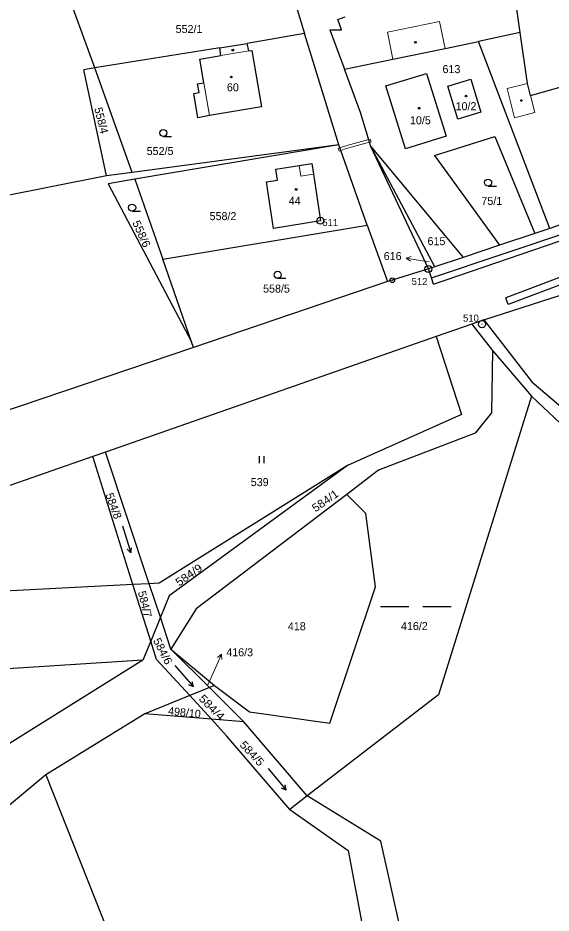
# Model space of a CAD drawing. Extents: x -664548 to -662415, y -1069720 to -1068208.
# Drawn here: x -663871.7 to -663758.5, y -1069095.9 to -1068905.8 of the extents above; entities that cross this region are included whole.
import ezdxf
from ezdxf.enums import TextEntityAlignment as Align

# ---------------------------------------------------------------- set-up
doc = ezdxf.new("R2010")
doc.units = 0
doc.header["$LTSCALE"] = 0.68
for name, color, linetype, lineweight in [('1', 7, 'Continuous', 25), ('13', 7, 'Continuous', 13), ('3', 7, 'Continuous', 25), ('4', 7, 'Continuous', 13), ('5', 7, 'Continuous', 25), ('7', 7, 'Continuous', 13), ('8', 7, 'Continuous', 25)]:
    doc.layers.add(name, color=color, linetype=linetype, lineweight=lineweight)
doc.layers.add('2', color=7, linetype='Continuous')

msp = doc.modelspace()

# ---------------------------------------------------------------- linework, layer by layer
at = {"layer": '1'}
for p, q in [((-663765.02, -1068908.87), (-663769.59, -1068876.23)), ((-663815.78, -1068892.97), (-663810.81, -1068909.09)), ((-663855.38, -1068916.4), (-663860.72, -1068901.56)), ((-663803.77, -1068906.09), (-663802.22, -1068905.52)), ((-663802.95, -1068908.29), (-663803.77, -1068906.09)), ((-663810.81, -1068909.09), (-663823.01, -1068911.18)), ((-663803.51, -1068932.74), (-663810.81, -1068909.09)), ((-663805.42, -1068908.29), (-663802.95, -1068908.29)), ((-663805.42, -1068908.29), (-663802.33, -1068916.65)), ((-663765.02, -1068908.87), (-663773.9, -1068910.78)), ((-663763.5, -1068919.69), (-663765.02, -1068908.87)), ((-663828.84, -1068912.12), (-663823.01, -1068911.18)), ((-663822.67, -1068912.77), (-663823.01, -1068911.18)), ((-663780.97, -1068912.24), (-663773.9, -1068910.78)), ((-663758.76, -1068950.5), (-663773.9, -1068910.78)), ((-663828.84, -1068912.12), (-663855.38, -1068916.4)), ((-663828.59, -1068913.77), (-663828.84, -1068912.12)), ((-663822.67, -1068912.77), (-663822.03, -1068912.67)), ((-663822.03, -1068912.67), (-663819.96, -1068924.67)), ((-663792.04, -1068914.52), (-663780.97, -1068912.24)), ((-663833.07, -1068914.53), (-663828.59, -1068913.77)), ((-663832.2, -1068919.56), (-663833.07, -1068914.53)), ((-663802.33, -1068916.65), (-663792.04, -1068914.52)), ((-663855.38, -1068916.4), (-663857.7, -1068916.78)), ((-663852.85, -1068939.32), (-663857.7, -1068916.78)), ((-663847.39, -1068938.59), (-663855.38, -1068916.4)), ((-663798.92, -1068925.89), (-663802.33, -1068916.65)), ((-663793.52, -1068920.22), (-663784.92, -1068917.55)), ((-663784.92, -1068917.55), (-663780.77, -1068930.91)), ((-663780.4, -1068920.27), (-663775.53, -1068918.77)), ((-663775.53, -1068918.77), (-663773.37, -1068925.8)), ((-663833.52, -1068919.79), (-663832.2, -1068919.56)), ((-663833.19, -1068921.64), (-663833.52, -1068919.79)), ((-663789.37, -1068933.59), (-663793.52, -1068920.22)), ((-663778.23, -1068927.31), (-663780.4, -1068920.27)), ((-663762.84, -1068922.22), (-663763.5, -1068919.69)), ((-663762.84, -1068922.22), (-663752.94, -1068919.42)), ((-663834.33, -1068921.82), (-663833.19, -1068921.64)), ((-663833.5, -1068926.99), (-663834.33, -1068921.82)), ((-663819.96, -1068924.67), (-663831, -1068926.53)), ((-663796.72, -1068933.1), (-663798.92, -1068925.89)), ((-663773.37, -1068925.8), (-663778.23, -1068927.31)), ((-663831, -1068926.53), (-663833.5, -1068926.99)), ((-663780.77, -1068930.91), (-663789.37, -1068933.59)), ((-663783.24, -1068935.02), (-663770.43, -1068930.97)), ((-663770.43, -1068930.97), (-663761.92, -1068951.55)), ((-663803.51, -1068932.74), (-663847.39, -1068938.59)), ((-663803.51, -1068932.74), (-663846.87, -1068940.04)), ((-663797.51, -1068949.76), (-663803.51, -1068932.74)), ((-663796.72, -1068933.1), (-663777.14, -1068956.63)), ((-663783.18, -1068958.64), (-663796.72, -1068933.1)), ((-663784.52, -1068959.09), (-663796.72, -1068933.1)), ((-663783.24, -1068935.02), (-663769.42, -1068954.05)), ((-663816.92, -1068937.88), (-663811.98, -1068937.12)), ((-663811.98, -1068937.12), (-663809.28, -1068936.71)), ((-663809.28, -1068936.71), (-663808.94, -1068938.96)), ((-663852.85, -1068939.32), (-663904.59, -1068949.64)), ((-663847.39, -1068938.59), (-663852.85, -1068939.32)), ((-663816.56, -1068940.2), (-663816.92, -1068937.88)), ((-663808.94, -1068938.96), (-663807.43, -1068948.85)), ((-663846.87, -1068940.04), (-663852.49, -1068940.99)), ((-663852.49, -1068940.99), (-663834.81, -1068974.56)), ((-663846.87, -1068940.04), (-663840.93, -1068957.04)), ((-663818.93, -1068940.59), (-663816.56, -1068940.2)), ((-663817.39, -1068950.47), (-663818.93, -1068940.59)), ((-663783.89, -1068961.01), (-663731.04, -1068943.25)), ((-663783.45, -1068962.35), (-663730.69, -1068944.3)), ((-663807.43, -1068948.85), (-663817.39, -1068950.47)), ((-663720.97, -1068947.42), (-663768.1, -1068965.24)), ((-663720.5, -1068948.84), (-663767.57, -1068966.64)), ((-663752.88, -1068948.45), (-663758.76, -1068950.5)), ((-663840.93, -1068957.04), (-663797.51, -1068949.76)), ((-663797.51, -1068949.76), (-663793.21, -1068961.78)), ((-663758.76, -1068950.5), (-663761.92, -1068951.55)), ((-663761.92, -1068951.55), (-663769.42, -1068954.05)), ((-663769.42, -1068954.05), (-663777.14, -1068956.63)), ((-663772.74, -1068969.94), (-663725.06, -1068954.55)), ((-663777.14, -1068956.63), (-663783.18, -1068958.64)), ((-663834.81, -1068974.56), (-663840.93, -1068957.04)), ((-663783.18, -1068958.64), (-663784.52, -1068959.09)), ((-663784.52, -1068959.09), (-663792.19, -1068961.5)), ((-663783.89, -1068961.01), (-663784.52, -1068959.09)), ((-663793.21, -1068961.78), (-663834.39, -1068975.76)), ((-663792.19, -1068961.5), (-663793.21, -1068961.78)), ((-663783.45, -1068962.35), (-663783.89, -1068961.01)), ((-663767.57, -1068966.64), (-663768.1, -1068965.24)), ((-663772.74, -1068969.94), (-663775.29, -1068970.83)), ((-663772.74, -1068969.94), (-663762.53, -1068983.07)), ((-663775.29, -1068970.83), (-663782.85, -1068973.47)), ((-663782.85, -1068973.47), (-663853.05, -1068997.99)), ((-663782.85, -1068973.47), (-663777.52, -1068990)), ((-663834.39, -1068975.76), (-663899.9, -1068997.91)), ((-663834.39, -1068975.76), (-663834.81, -1068974.56)), ((-663770.9, -1068976.39), (-663762.6, -1068986.14)), ((-663762.53, -1068983.07), (-663748.36, -1068995.22)), ((-663762.6, -1068986.14), (-663782.35, -1069049.55)), ((-663762.6, -1068986.14), (-663750.68, -1068997.45)), ((-663777.52, -1068990), (-663801.7, -1069000.84)), ((-663771.11, -1068989.7), (-663774.57, -1068993.97)), ((-663774.57, -1068993.97), (-663795.13, -1069001.88)), ((-663853.05, -1068997.99), (-663855.8, -1068998.95)), ((-663843.78, -1069025.98), (-663853.05, -1068997.99)), ((-663855.8, -1068998.95), (-663894.44, -1069012.45)), ((-663847.26, -1069026.15), (-663855.8, -1068998.95)), ((-663801.7, -1069000.84), (-663841.7, -1069025.88)), ((-663801.7, -1069000.84), (-663839.6, -1069028.51)), ((-663795.13, -1069001.88), (-663801.83, -1069006.98)), ((-663801.83, -1069006.98), (-663833.81, -1069031.33)), ((-663797.83, -1069011.05), (-663801.83, -1069006.98)), ((-663795.78, -1069026.6), (-663797.83, -1069011.05)), ((-663847.26, -1069026.15), (-663875.95, -1069027.59)), ((-663843.78, -1069025.98), (-663847.26, -1069026.15)), ((-663843.49, -1069038.15), (-663847.26, -1069026.15)), ((-663841.7, -1069025.88), (-663843.78, -1069025.98)), ((-663841.44, -1069033.06), (-663843.78, -1069025.98)), ((-663805.46, -1069055.59), (-663795.78, -1069026.6)), ((-663839.6, -1069028.51), (-663841.44, -1069033.06)), ((-663833.81, -1069031.33), (-663839.18, -1069039.89)), ((-663841.44, -1069033.06), (-663843.49, -1069038.15)), ((-663839.18, -1069039.89), (-663841.44, -1069033.06)), ((-663843.49, -1069038.15), (-663845.14, -1069042.24)), ((-663842.26, -1069042.07), (-663843.49, -1069038.15)), ((-663830.98, -1069048.05), (-663839.18, -1069039.89)), ((-663839.18, -1069039.89), (-663829.93, -1069047.62)), ((-663845.14, -1069042.24), (-663902.32, -1069045.83)), ((-663845.14, -1069042.24), (-663874.07, -1069060.3)), ((-663835.19, -1069049.75), (-663842.26, -1069042.07)), ((-663830.98, -1069048.05), (-663835.19, -1069049.75)), ((-663829.93, -1069047.62), (-663830.98, -1069048.05)), ((-663823.71, -1069055.28), (-663830.98, -1069048.05)), ((-663829.93, -1069047.62), (-663822.51, -1069053.21)), ((-663835.19, -1069049.75), (-663844.7, -1069053.6)), ((-663830.61, -1069054.73), (-663835.19, -1069049.75)), ((-663782.35, -1069049.55), (-663810.24, -1069071.06)), ((-663844.7, -1069053.6), (-663865.77, -1069066.56)), ((-663830.61, -1069054.73), (-663844.7, -1069053.6)), ((-663822.51, -1069053.21), (-663805.46, -1069055.59)), ((-663823.71, -1069055.28), (-663830.61, -1069054.73)), ((-663827.29, -1069058.33), (-663830.61, -1069054.73)), ((-663810.24, -1069071.06), (-663823.71, -1069055.28)), ((-663813.97, -1069073.94), (-663827.29, -1069058.33)), ((-663865.77, -1069066.56), (-663883.87, -1069081.66)), ((-663865.77, -1069066.56), (-663839.98, -1069131.55)), ((-663810.24, -1069071.06), (-663813.97, -1069073.94)), ((-663794.6, -1069080.65), (-663810.24, -1069071.06)), ((-663813.97, -1069073.94), (-663801.58, -1069082.65)), ((-663790.14, -1069100.67), (-663794.6, -1069080.65)), ((-663801.58, -1069082.65), (-663798.08, -1069101.18))]:
    msp.add_line(p, q, dxfattribs=at)
msp.add_lwpolyline([(-663775.29, -1068970.83), (-663770.9, -1068976.39), (-663771.11, -1068989.7)], dxfattribs=at)
at = {"layer": '13'}
for points in [[(-663800.89, -1068933.24), (-663797.01, -1068932.16), (-663797.18, -1068931.58), (-663801.05, -1068932.66), (-663802.5, -1068933.06), (-663803.29, -1068933.36), (-663803.09, -1068933.93), (-663802.38, -1068933.66)], [(-663796.85, -1068931.49), (-663797.18, -1068931.58), (-663797.01, -1068932.16), (-663796.69, -1068932.07)], [(-663803.47, -1068934.07), (-663803.09, -1068933.93), (-663803.29, -1068933.36), (-663803.68, -1068933.5)]]:
    msp.add_lwpolyline(points, close=True, dxfattribs=at)
at = {"layer": '3'}
for p, q in [((-663840.803, -1068930.96), (-663839.053, -1068930.96)), ((-663771.833, -1068941.5), (-663770.083, -1068941.5)), ((-663847.423, -1068946.82), (-663845.673, -1068946.82)), ((-663816.533, -1068961.08), (-663814.783, -1068961.08)), ((-663820.401, -1069000.36), (-663820.401, -1068998.86)), ((-663819.4, -1069000.36), (-663819.4, -1068998.86)), ((-663847.726, -1069019.398), (-663848.491, -1069018.61)), ((-663794.669, -1069030.84), (-663788.669, -1069030.84)), ((-663785.669, -1069030.84), (-663779.669, -1069030.84)), ((-663834.407, -1069047.863), (-663835.427, -1069047.454)), ((-663814.687, -1069069.797), (-663815.699, -1069069.371))]:
    msp.add_line(p, q, dxfattribs=at)
for points in [[(-663849.48, -1069013.66), (-663847.726, -1069019.398), (-663847.532, -1069018.317)], [(-663838.343, -1069043.334), (-663834.407, -1069047.863), (-663834.67, -1069046.796)], [(-663818.544, -1069065.201), (-663814.687, -1069069.797), (-663814.931, -1069068.726)]]:
    msp.add_lwpolyline(points, dxfattribs=at)
for centre in [(-663840.8029, -1068930.2098), (-663771.8329, -1068940.7498), (-663847.4229, -1068946.0698), (-663816.5329, -1068960.3298)]:
    msp.add_circle(centre, 0.75, dxfattribs=at)
at = {"layer": '4'}
for p, q in [((-663793.2, -1068908.77), (-663782.13, -1068906.53)), ((-663780.97, -1068912.24), (-663782.13, -1068906.53)), ((-663792.04, -1068914.52), (-663793.2, -1068908.77)), ((-663828.59, -1068913.77), (-663822.67, -1068912.77)), ((-663831, -1068926.53), (-663832.2, -1068919.56)), ((-663763.5, -1068919.69), (-663767.79, -1068920.79)), ((-663767.79, -1068920.79), (-663766.21, -1068926.97)), ((-663761.9, -1068925.87), (-663762.84, -1068922.22)), ((-663761.9, -1068925.87), (-663766.21, -1068926.97)), ((-663811.98, -1068937.12), (-663811.63, -1068939.42)), ((-663811.63, -1068939.42), (-663808.94, -1068938.96))]:
    msp.add_line(p, q, dxfattribs=at)
at = {"layer": '5'}
for centre in [(-663787.2568, -1068910.9492), (-663826.0568, -1068912.5992), (-663826.3468, -1068918.3292), (-663776.5368, -1068922.3792), (-663764.7668, -1068923.3092), (-663786.4668, -1068924.9492), (-663812.5968, -1068942.2092)]:
    msp.add_circle(centre, 0.175, dxfattribs=at)
at = {"layer": '7'}
for p, q in [((-663789.214, -1068956.811), (-663788.303, -1068957.462)), ((-663828.449, -1069040.958), (-663829.314, -1069041.67))]:
    msp.add_line(p, q, dxfattribs=at)
for points in [[(-663784.35, -1068957.6), (-663786.25, -1068957.28), (-663789.214, -1068956.811), (-663788.147, -1068956.473)], [(-663831.36, -1069047.44), (-663829.67, -1069043.7), (-663828.449, -1069040.958), (-663828.399, -1069042.077)]]:
    msp.add_lwpolyline(points, dxfattribs=at)
at = {"layer": '8'}
for centre, radius in [((-663807.45, -1068948.8498), 0.75), ((-663807.45, -1068948.8498), 0.03), ((-663784.53, -1068959.0998), 0.75), ((-663784.53, -1068959.0998), 0.03), ((-663792.19, -1068961.4999), 0.5), ((-663792.19, -1068961.4999), 0.0303), ((-663773.13, -1068970.8298), 0.75), ((-663773.13, -1068970.8298), 0.03)]:
    msp.add_circle(centre, radius, dxfattribs=at)

# ---------------------------------------------------------------- texts
at = {"layer": '2'}
for s, p in [('552/1', (-663838.19, -1068908.975)), ('613', (-663781.52, -1068917.495)), ('60', (-663827.3, -1068921.354)), ('10/2', (-663778.74, -1068925.375)), ('10/5', (-663788.43, -1068928.365)), ('552/5', (-663844.34, -1068934.895)), ('44', (-663814.17, -1068945.455)), ('75/1', (-663773.26, -1068945.495)), ('558/2', (-663830.98, -1068948.725)), ('615', (-663784.7, -1068954.045)), ('558/5', (-663819.62, -1068964.125)), ('539', (-663822.24, -1069005.235)), ('418', (-663814.36, -1069035.854)), ('416/2', (-663790.34, -1069035.814)), ('416/3', (-663827.44, -1069041.385))]:
    msp.add_text(s, height=1.7, dxfattribs=at).set_placement(p)
for s, rotation, p in [('558/4', 284, (-663855.492, -1068924.992)), ('584/8', 290, (-663853.119, -1069007.055)), ('584/7', 284, (-663846.222, -1069027.752)), ('498/10', 354, (-663839.864, -1069053.792))]:
    msp.add_text(s, height=1.7, rotation=rotation, dxfattribs=at).set_placement(p)
for s, rotation, width, p in [('558/6', 294, 1.05, (-663847.418, -1068949.252)), ('584/1', 35, 1.1, (-663808.506, -1069010.838)), ('584/9', 35, 1.1, (-663837.466, -1069026.598)), ('584/6', 297, 1.05, (-663843.028, -1069038.022)), ('584/4', 315, 1.15, (-663833.42, -1069050.54)), ('584/5', 313, 1.1, (-663824.73, -1069060.319))]:
    msp.add_text(s, height=1.7, rotation=rotation, dxfattribs=dict(at, width=width)).set_placement(p)
msp.add_text('616', height=1.7, dxfattribs=at).set_placement((-663790.209, -1068957.215), align=Align.RIGHT)
at = {"layer": '8'}
for s, p in [('511', (-663803.688, -1068949.985)), ('512', (-663784.729, -1068962.507)), ('510', (-663773.809, -1068970.287))]:
    msp.add_text(s, height=1.5, dxfattribs=at).set_placement(p, align=Align.RIGHT)

doc.saveas('drawing.dxf')
